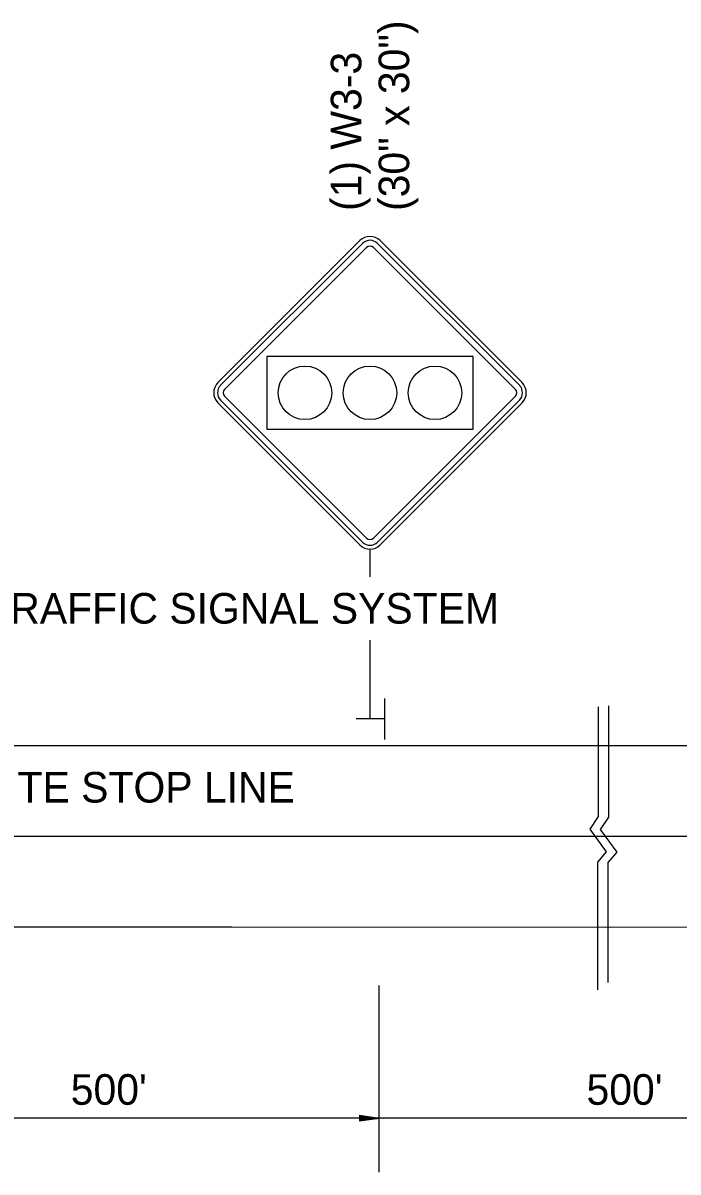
# Model space of a CAD drawing. Extents: x 1930579 to 1934718, y 596452 to 597844.
# Drawn here: x 1932491.9 to 1932620.3, y 596831.7 to 597057 of the extents above; entities that cross this region are included whole.
import ezdxf

# ---------------------------------------------------------------- set-up
doc = ezdxf.new("R2010")
doc.units = 0
for name, color, linetype in [('Default', 7, 'Continuous'), ('P_TC_Signs_Permanent', 7, 'Continuous'), ('R_Annotation', 7, 'Continuous')]:
    doc.layers.add(name, color=color, linetype=linetype)

msp = doc.modelspace()

# ---------------------------------------------------------------- linework, layer by layer
at = {"layer": 'Default'}
for p, q in [((1932562.78, 596924.51), (1932562.78, 596916.5)), ((1932562.66, 596920.53), (1932557.19, 596920.53)), ((1932378.86, 596915.33), (1932993.57, 596915.28)), ((1932378.14, 596897.54), (1933095.76, 596897.49)), ((1932378.64, 596879.75), (1932532.75, 596879.75)), ((1932378.64, 596879.75), (1932993.57, 596879.7)), ((1932561.71, 596831.69), (1932561.71, 596868.29)), ((1932561.71, 596842.28), (1932460.58, 596842.28)), ((1932557.87, 596842.85), (1932561.71, 596842.28)), ((1932557.87, 596842.85), (1932557.87, 596841.7)), ((1932557.87, 596842.76), (1932561.07, 596842.28)), ((1932557.87, 596842.66), (1932560.41, 596842.28)), ((1932557.87, 596842.56), (1932559.77, 596842.28)), ((1932557.87, 596842.46), (1932559.12, 596842.28)), ((1932557.87, 596842.37), (1932558.48, 596842.28)), ((1932557.87, 596841.7), (1932561.71, 596842.28)), ((1932557.87, 596842.09), (1932559.12, 596842.28)), ((1932557.87, 596841.89), (1932560.41, 596842.28)), ((1932557.87, 596841.8), (1932561.07, 596842.28)), ((1932557.87, 596841.99), (1932559.77, 596842.28)), ((1932557.87, 596842.19), (1932558.48, 596842.28)), ((1932660.61, 596842.28), (1932560.85, 596842.28))]:
    msp.add_line(p, q, dxfattribs=at)
for points in [[(1932604.68, 596922.91), (1932604.68, 596901.39), (1932603.02, 596898.92), (1932606.25, 596894.49), (1932604.55, 596892.44), (1932604.55, 596867.41)], [(1932606.72, 596923.11), (1932606.72, 596901.3), (1932605.06, 596898.83), (1932608.3, 596894.4), (1932606.59, 596892.36), (1932606.59, 596868.85)]]:
    msp.add_lwpolyline(points, dxfattribs=at)
at = {"layer": 'P_TC_Signs_Permanent'}
for p, q in [((1932530.1, 596986.48), (1932557.94, 597014.32)), ((1932530.63, 596985.95), (1932558.47, 597013.79)), ((1932559.26, 597012.99), (1932531.42, 596985.15)), ((1932588.43, 596985.15), (1932560.59, 597012.99)), ((1932561.38, 597013.79), (1932589.23, 596985.95)), ((1932561.91, 597014.32), (1932589.76, 596986.48)), ((1932531.42, 596983.82), (1932559.26, 596955.98)), ((1932560.59, 596955.98), (1932588.43, 596983.82)), ((1932557.94, 596954.66), (1932530.1, 596982.5)), ((1932558.47, 596955.19), (1932530.63, 596983.03)), ((1932589.23, 596983.03), (1932561.38, 596955.19)), ((1932589.76, 596982.5), (1932561.91, 596954.66))]:
    msp.add_line(p, q, dxfattribs=at)
msp.add_lwpolyline([(1932580.17, 596977.36), (1932580.17, 596991.61), (1932539.67, 596991.61), (1932539.67, 596977.36)], close=True, dxfattribs=at)
for centre in [(1932547.17, 596984.49), (1932559.92, 596984.49), (1932572.67, 596984.49)]:
    msp.add_circle(centre, 5.25, dxfattribs=at)
for centre, radius, start, end in [((1932559.93, 597012.33), 2.81, 45, 135), ((1932559.93, 597012.33), 2.06, 45, 135), ((1932559.93, 597012.33), 0.938, 45, 135), ((1932532.08, 596984.49), 2.81, 135, 225), ((1932532.08, 596984.49), 2.06, 135, 225), ((1932587.77, 596984.49), 2.06, 315, 45), ((1932587.77, 596984.49), 2.81, 315, 45), ((1932532.08, 596984.49), 0.938, 135, 225), ((1932587.77, 596984.49), 0.938, 315, 45), ((1932559.93, 596956.65), 2.81, 225, 315), ((1932559.93, 596956.65), 2.06, 225, 315), ((1932559.93, 596956.65), 0.938, 225, 315)]:
    msp.add_arc(centre, radius, start, end, dxfattribs=at)
at = {"layer": 'R_Annotation'}
for p, q in [((1932559.93, 596948.42), (1932559.93, 596953.83)), ((1932559.93, 596920.53), (1932559.93, 596935.99))]:
    msp.add_line(p, q, dxfattribs=at)

# ---------------------------------------------------------------- texts
at = {"layer": 'Default'}
for s, height, p in [('PORTABLE TRAFFIC SIGNAL SYSTEM', 6, (1932439.45, 596939.23)), ('12" WHITE STOP LINE', 5.9996, (1932461.21, 596904.14)), ("500'", 6, (1932501.24, 596844.88)), ("500'", 6, (1932602.38, 596844.88))]:
    msp.add_text(s, height=height, rotation=360, dxfattribs=at).set_placement(p)
at = {"layer": 'R_Annotation'}
for s, height, p in [('(30" x 30")', 5.9996, (1932567.61, 597020.14)), ('(1) W3-3', 6, (1932558.24, 597020.14))]:
    msp.add_text(s, height=height, rotation=90, dxfattribs=at).set_placement(p)

doc.saveas('drawing.dxf')
